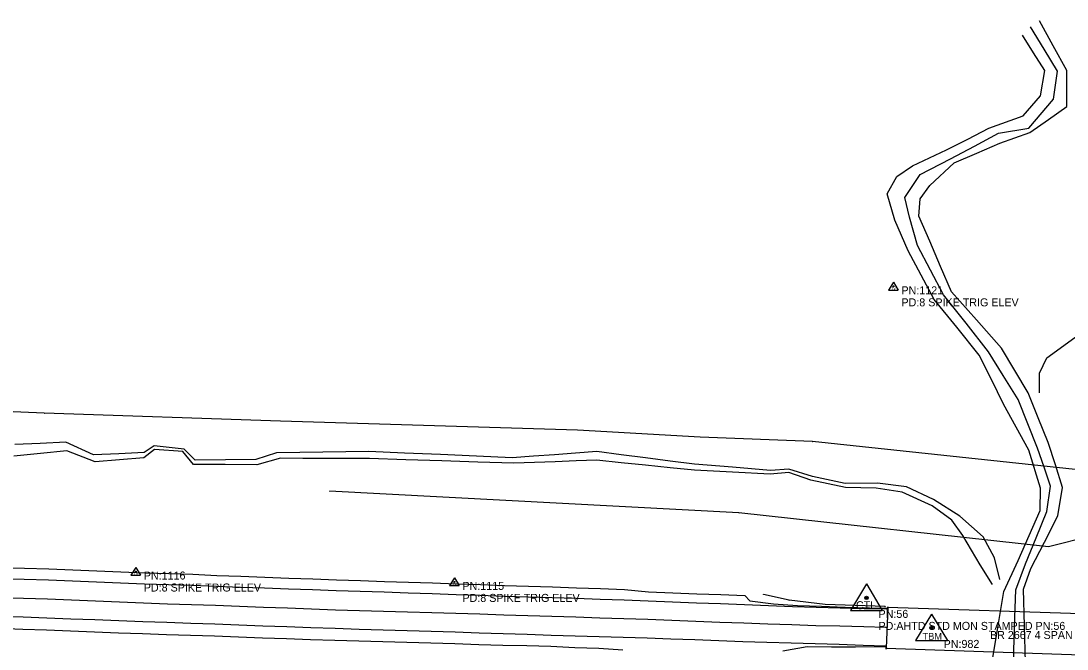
# Model space of a CAD drawing. Extents: x 976456 to 985170, y 1525951 to 1527080.
# Drawn here: x 977415 to 978069, y 1526484 to 1526877 of the extents above; entities that cross this region are included whole.
import ezdxf

# ---------------------------------------------------------------- set-up
doc = ezdxf.new("R2010")
doc.units = 0
for name, color, linetype in [('S_BRIDGE', 7, 'Continuous'), ('S_DITCHLINE', 7, 'Continuous'), ('S_EDGE_PAVEMENT', 7, 'Continuous'), ('S_FENCE', 7, 'Continuous'), ('S_FIBER_OPTIC_CABLE', 7, 'Continuous'), ('S_GUARDRAIL', 7, 'Continuous'), ('S_MSC_PT_SYM', 7, 'Continuous'), ('S_PAVEMENT_CROWN', 7, 'Continuous'), ('S_PRIMARY_CTL', 7, 'Continuous'), ('S_PRIMARY_CTL_ANNOT', 7, 'Continuous'), ('S_RDW_PT_SYM', 7, 'Continuous'), ('S_SECONDARY_CTL', 7, 'Continuous'), ('S_SECONDARY_CTL_ANNOT', 7, 'Continuous'), ('S_SHOULDER', 7, 'Continuous'), ('S_STR_PT_SYM', 7, 'Continuous'), ('S_STREAM', 7, 'Continuous'), ('S_SURVEY_TEXT_ANNOT', 7, 'Continuous'), ('S_UTL_PT_SYM', 7, 'Continuous')]:
    doc.layers.add(name, color=color, linetype=linetype)

msp = doc.modelspace()

# ---------------------------------------------------------------- linework, layer by layer
at = {"layer": 'S_BRIDGE'}
for p, q in [((977956.8, 1526510.36), (977955.86, 1526484.94)), ((978086.33, 1526506.14), (977956.8, 1526510.36)), ((977955.86, 1526484.94), (978085.38, 1526480.48))]:
    msp.add_line(p, q, dxfattribs=at)
at = {"layer": 'S_DITCHLINE'}
for points in [[(978022.11, 1526524.86), (978014.39, 1526537.02), (978003.69, 1526555.36), (977996.69, 1526565.09), (977984.55, 1526573.85), (977965.71, 1526582.4), (977949.52, 1526585.06), (977930.38, 1526585.35), (977908.76, 1526589.99), (977894.9, 1526594.7), (977883.34, 1526593.71), (977859.69, 1526594.95), (977836.03, 1526596.19), (977820.78, 1526597.75), (977805.53, 1526599.32), (977790.28, 1526600.89), (977775.03, 1526602.46), (977762.07, 1526601.98), (977749.12, 1526601.51), (977736.16, 1526601.04), (977723.21, 1526600.56), (977700.7, 1526601.29), (977678.19, 1526602.02), (977655.68, 1526602.75), (977633.17, 1526603.48), (977619.27, 1526603.52), (977605.36, 1526603.56), (977591.46, 1526603.6), (977577.56, 1526603.64), (977562.67, 1526599.67), (977542.95, 1526599.76), (977523.23, 1526599.86), (977516.49, 1526607.97), (977498.76, 1526609.15), (977492.06, 1526604.02), (977476.91, 1526602.69), (977461.76, 1526601.35), (977444.09, 1526608.43), (977427.49, 1526606.7), (977410.9, 1526604.96)], [(978026.79, 1526527.94), (978023.47, 1526541.45), (978016.39, 1526554.51), (978001.68, 1526567.51), (977985.38, 1526577.96), (977968.53, 1526585.8), (977950.35, 1526588.02), (977930.07, 1526587.85), (977909.81, 1526592.38), (977894.95, 1526596.84), (977883.6, 1526596.13), (977859.81, 1526598.05), (977836.03, 1526599.97), (977820.78, 1526601.94), (977805.53, 1526603.9), (977790.28, 1526605.86), (977775.03, 1526607.82), (977761.83, 1526606.87), (977748.62, 1526605.91), (977735.42, 1526604.95), (977722.21, 1526603.99), (977699.82, 1526604.98), (977677.42, 1526605.98), (977655.02, 1526606.97), (977632.63, 1526607.96), (977618.24, 1526607.75), (977603.85, 1526607.54), (977589.46, 1526607.33), (977575.08, 1526607.12), (977562.04, 1526602.91), (977543.17, 1526602.75), (977524.29, 1526602.59), (977517.31, 1526609.38), (977498.63, 1526611.49), (977492.41, 1526607.25), (977476.58, 1526606.54), (977460.76, 1526605.83), (977443.38, 1526613.68), (977427.48, 1526612.95), (977411.59, 1526612.21)]]:
    msp.add_lwpolyline(points, dxfattribs=at)
at = {"layer": 'S_EDGE_PAVEMENT'}
for points in [[(977402.36, 1526528.58), (977417.36, 1526528.07), (977432.54, 1526527.67), (977447.52, 1526527.06), (977462.51, 1526526.49), (977477.5, 1526525.88), (977492.49, 1526525.22), (977492.49, 1526525.22), (977492.49, 1526525.22), (977507.48, 1526524.75), (977522.45, 1526524.33), (977537.44, 1526523.77), (977552.43, 1526523.2), (977567.41, 1526522.62), (977582.4, 1526522.05), (977597.4, 1526521.6), (977597.4, 1526521.6), (977597.4, 1526521.6), (977612.28, 1526521.1), (977627.27, 1526520.57), (977642.26, 1526520.12), (977657.26, 1526519.63), (977672.24, 1526519.08), (977687.24, 1526518.58), (977702.26, 1526518.14), (977717.24, 1526517.58), (977732.24, 1526517.11), (977747.23, 1526516.64), (977762.22, 1526516.17), (977777.21, 1526515.69), (977792.2, 1526515.09), (977807.2, 1526514.63), (977822.29, 1526513.91), (977837.28, 1526513.41), (977852.27, 1526512.82), (977867.26, 1526512.19), (977882.25, 1526511.59), (977897.24, 1526511.04), (977912.07, 1526510.62), (977927.06, 1526510.2), (977942.06, 1526509.83), (977955.73, 1526509.47), (977956.7, 1526509.44)], [(977401.76, 1526505.02), (977416.76, 1526504.51), (977431.59, 1526504.02), (977446.58, 1526503.41), (977461.57, 1526502.84), (977476.56, 1526502.24), (977491.55, 1526501.71), (977506.54, 1526501.17), (977521.56, 1526500.69), (977536.55, 1526500.16), (977536.55, 1526500.16), (977551.54, 1526499.62), (977551.54, 1526499.62), (977566.52, 1526498.98), (977581.52, 1526498.47), (977596.51, 1526497.91), (977611.58, 1526497.39), (977626.58, 1526496.95), (977641.57, 1526496.49), (977641.57, 1526496.49), (977656.56, 1526496.05), (977671.56, 1526495.6), (977686.55, 1526495.16), (977701.52, 1526494.63), (977716.51, 1526494.13), (977731.5, 1526493.66), (977746.5, 1526493.17), (977761.49, 1526492.7), (977776.48, 1526492.31), (977791.48, 1526491.84), (977806.47, 1526491.38), (977821.37, 1526490.89), (977836.36, 1526490.32), (977851.35, 1526489.72), (977866.34, 1526489.23), (977881.33, 1526488.63), (977896.33, 1526488.24), (977911.45, 1526487.85), (977911.45, 1526487.85), (977911.45, 1526487.85), (977926.44, 1526487.39), (977941.44, 1526486.92), (977955.14, 1526486.51), (977955.78, 1526486.49)]]:
    msp.add_lwpolyline(points, dxfattribs=at)
at = {"layer": 'S_FENCE'}
for p, q in [((977429.97, 1526631.95), (977214.88, 1526641.2)), ((977577.45, 1526626.9), (977429.97, 1526631.95)), ((977762.93, 1526621.31), (977577.45, 1526626.9)), ((977839.57, 1526616.88), (977762.93, 1526621.31)), ((977909.7, 1526614.16), (977839.57, 1526616.88)), ((978230.77, 1526580), (977909.7, 1526614.16))]:
    msp.add_line(p, q, dxfattribs=at)
at = {"layer": 'S_FIBER_OPTIC_CABLE'}
for p, q in [((977863.85, 1526569.6), (977608.15, 1526583.08)), ((978057.17, 1526548.34), (977863.85, 1526569.6)), ((978103.59, 1526560.21), (978057.17, 1526548.34))]:
    msp.add_line(p, q, dxfattribs=at)
at = {"layer": 'S_GUARDRAIL'}
for p, q in [((977895.11, 1526515.01), (977879.11, 1526518.44)), ((977917.64, 1526512.3), (977895.11, 1526515.01)), ((977955.08, 1526510.96), (977917.64, 1526512.3))]:
    msp.add_line(p, q, dxfattribs=at)
at = {"layer": 'S_MSC_PT_SYM'}
for points in [[(977429.97, 1526631.95), (977429.97, 1526632), (977429.97, 1526631.95), (977429.92, 1526631.95), (977429.97, 1526631.95), (977429.97, 1526631.9), (977429.97, 1526631.95), (977430.02, 1526631.95)], [(977577.45, 1526626.9), (977577.45, 1526626.95), (977577.45, 1526626.9), (977577.4, 1526626.9), (977577.45, 1526626.9), (977577.45, 1526626.85), (977577.45, 1526626.9), (977577.5, 1526626.9)], [(977762.93, 1526621.31), (977762.93, 1526621.36), (977762.93, 1526621.31), (977762.88, 1526621.31), (977762.93, 1526621.31), (977762.93, 1526621.26), (977762.93, 1526621.31), (977762.98, 1526621.31)], [(977839.57, 1526616.88), (977839.57, 1526616.93), (977839.57, 1526616.88), (977839.52, 1526616.88), (977839.57, 1526616.88), (977839.57, 1526616.83), (977839.57, 1526616.88), (977839.62, 1526616.88)], [(977909.7, 1526614.16), (977909.7, 1526614.21), (977909.7, 1526614.16), (977909.65, 1526614.16), (977909.7, 1526614.16), (977909.7, 1526614.11), (977909.7, 1526614.16), (977909.75, 1526614.16)], [(978020.61, 1526495.7), (978020.61, 1526495.75), (978020.61, 1526495.7), (978020.56, 1526495.7), (978020.61, 1526495.7), (978020.61, 1526495.65), (978020.61, 1526495.7), (978020.66, 1526495.7)]]:
    msp.add_lwpolyline(points, dxfattribs=at)
at = {"layer": 'S_PAVEMENT_CROWN'}
for points in [[(977402.06, 1526516.56), (977417.05, 1526516.17), (977432.06, 1526515.75), (977447.05, 1526515.1), (977462.04, 1526514.51), (977477.02, 1526513.91), (977492.01, 1526513.34), (977507, 1526512.79), (977521.99, 1526512.31), (977536.99, 1526511.83), (977551.97, 1526511.25), (977566.96, 1526510.69), (977581.95, 1526510.12), (977596.94, 1526509.56), (977611.92, 1526509.01), (977626.92, 1526508.57), (977641.91, 1526508.13), (977656.91, 1526507.71), (977671.9, 1526507.28), (977686.89, 1526506.83), (977701.89, 1526506.34), (977716.88, 1526505.87), (977731.87, 1526505.4), (977746.86, 1526504.93), (977761.86, 1526504.47), (977776.85, 1526503.94), (977791.84, 1526503.48), (977806.83, 1526503.01), (977821.83, 1526502.45), (977836.82, 1526501.87), (977851.81, 1526501.28), (977866.8, 1526500.77), (977881.79, 1526500.18), (977896.78, 1526499.72), (977911.76, 1526499.24), (977926.75, 1526498.86), (977941.75, 1526498.5), (977955.44, 1526498.14)], [(977955.44, 1526498.14), (977956.23, 1526498.12)]]:
    msp.add_lwpolyline(points, dxfattribs=at)
at = {"layer": 'S_PRIMARY_CTL'}
for p, q in [((977943.49, 1526525.1), (977933.46, 1526508.59)), ((977943.49, 1526525.1), (977953.32, 1526508.59)), ((977933.46, 1526508.59), (977953.32, 1526508.59)), ((977984.17, 1526506.33), (977974.13, 1526489.82)), ((977984.17, 1526506.33), (977993.99, 1526489.82)), ((977974.13, 1526489.82), (977993.99, 1526489.82))]:
    msp.add_line(p, q, dxfattribs=at)
for centre, radius in [((977943.49, 1526516.4), 1.04), ((977943.49, 1526516.4), 0.609), ((977943.49, 1526516.4), 0.344), ((977984.17, 1526497.63), 1.04), ((977984.17, 1526497.63), 0.609), ((977984.17, 1526497.63), 0.344)]:
    msp.add_circle(centre, radius, dxfattribs=at)
at = {"layer": 'S_RDW_PT_SYM'}
for points in [[(977879.11, 1526518.44), (977879.11, 1526518.49), (977879.11, 1526518.44), (977879.06, 1526518.44), (977879.11, 1526518.44), (977879.11, 1526518.39), (977879.11, 1526518.44), (977879.16, 1526518.44)], [(977895.11, 1526515.01), (977895.11, 1526515.06), (977895.11, 1526515.01), (977895.06, 1526515.01), (977895.11, 1526515.01), (977895.11, 1526514.96), (977895.11, 1526515.01), (977895.16, 1526515.01)], [(977917.64, 1526512.3), (977917.64, 1526512.35), (977917.64, 1526512.3), (977917.59, 1526512.3), (977917.64, 1526512.3), (977917.64, 1526512.25), (977917.64, 1526512.3), (977917.69, 1526512.3)], [(977955.08, 1526510.96), (977955.08, 1526511.01), (977955.08, 1526510.96), (977955.03, 1526510.96), (977955.08, 1526510.96), (977955.08, 1526510.91), (977955.08, 1526510.96), (977955.13, 1526510.96)]]:
    msp.add_lwpolyline(points, dxfattribs=at)
at = {"layer": 'S_SECONDARY_CTL'}
for p, q in [((977960.32, 1526713.76), (977957.31, 1526708.81)), ((977960.32, 1526713.76), (977963.26, 1526708.81)), ((977957.31, 1526708.81), (977963.26, 1526708.81)), ((977487.11, 1526535.5), (977484.1, 1526530.55)), ((977484.1, 1526530.55), (977490.05, 1526530.55)), ((977487.11, 1526535.5), (977490.05, 1526530.55)), ((977686.13, 1526529), (977683.12, 1526524.05)), ((977683.12, 1526524.05), (977689.08, 1526524.05)), ((977686.13, 1526529), (977689.08, 1526524.05))]:
    msp.add_line(p, q, dxfattribs=at)
for centre, radius in [((977960.32, 1526711.15), 0.311), ((977960.32, 1526711.15), 0.183), ((977960.32, 1526711.15), 0.103), ((977487.11, 1526532.89), 0.311), ((977487.11, 1526532.89), 0.183), ((977487.11, 1526532.89), 0.103), ((977686.13, 1526526.39), 0.311), ((977686.13, 1526526.39), 0.183), ((977686.13, 1526526.39), 0.103)]:
    msp.add_circle(centre, radius, dxfattribs=at)
at = {"layer": 'S_SHOULDER'}
for points in [[(977402.54, 1526535.38), (977417.53, 1526534.88), (977432.81, 1526534.48), (977447.8, 1526533.86), (977462.78, 1526533.3), (977477.77, 1526532.68), (977492.76, 1526532.03), (977507.75, 1526531.55), (977522.7, 1526531.13), (977537.69, 1526530.45), (977552.68, 1526529.88), (977567.67, 1526529.3), (977582.66, 1526528.74), (977597.65, 1526528.28), (977612.48, 1526527.79), (977627.47, 1526527.26), (977642.46, 1526526.74), (977657.45, 1526526.25), (977672.44, 1526525.71), (977687.43, 1526525.23), (977702.46, 1526524.79), (977717.45, 1526524.23), (977732.45, 1526523.76), (977747.44, 1526523.26), (977762.43, 1526522.78), (977777.42, 1526522.29), (977792.41, 1526521.67), (977807.37, 1526520.24), (977822.52, 1526519.49), (977837.51, 1526519.03), (977852.5, 1526518.44), (977867.48, 1526517.81), (977870.55, 1526514.59), (977885.49, 1526512.72), (977900.46, 1526511.7), (977915.28, 1526511.3), (977930.26, 1526510.64), (977945.26, 1526510.28), (977956.71, 1526509.97)], [(977401.58, 1526497.45), (977416.57, 1526496.94), (977431.3, 1526496.4), (977446.29, 1526495.8), (977461.28, 1526495.23), (977476.27, 1526494.64), (977491.26, 1526494.11), (977506.25, 1526493.57), (977521.28, 1526493.14), (977536.27, 1526492.58), (977551.26, 1526492.05), (977566.25, 1526491.49), (977581.24, 1526490.97), (977596.23, 1526490.42), (977611.37, 1526489.89), (977626.36, 1526489.54), (977641.36, 1526489.16), (977656.35, 1526488.72), (977671.35, 1526488.27), (977686.34, 1526487.82), (977701.3, 1526487.26), (977716.3, 1526486.94), (977731.3, 1526486.74), (977746.29, 1526486.19), (977761.27, 1526485.48), (977776.26, 1526484.99), (977791.24, 1526483.97)], [(977891.25, 1526483.24), (977906.37, 1526485.99), (977921.53, 1526485.81), (977936.53, 1526485.74), (977951.54, 1526485.98), (977955.77, 1526485.87)]]:
    msp.add_lwpolyline(points, dxfattribs=at)
at = {"layer": 'S_STR_PT_SYM'}
for points in [[(977956.8, 1526510.36), (977956.8, 1526510.86), (977956.8, 1526510.36), (977956.3, 1526510.36), (977956.8, 1526510.36), (977956.8, 1526509.86), (977956.8, 1526510.36), (977957.3, 1526510.36)], [(977955.86, 1526484.94), (977955.86, 1526485.44), (977955.86, 1526484.94), (977955.36, 1526484.94), (977955.86, 1526484.94), (977955.86, 1526484.44), (977955.86, 1526484.94), (977956.36, 1526484.94)]]:
    msp.add_lwpolyline(points, dxfattribs=at)
at = {"layer": 'S_STREAM'}
for points in [[(978042.77, 1526476.04), (978042.11, 1526498.99), (978041.46, 1526521.94), (978046.14, 1526534.73), (978054.59, 1526551.18), (978063.04, 1526567.63), (978065.84, 1526585.49), (978061.44, 1526599.54), (978057.05, 1526613.59), (978050.72, 1526629.05), (978044.4, 1526644.5), (978036.13, 1526658.53), (978027.86, 1526672.55), (978012.22, 1526690.17), (977996.58, 1526707.8), (977989.77, 1526723.64), (977982.96, 1526739.48), (977976.2, 1526755.05), (977976.91, 1526765.91), (977983.05, 1526774.18), (977998.21, 1526788.4), (978012.49, 1526794.5), (978026.77, 1526800.6), (978045.58, 1526807.33), (978057.12, 1526815.43), (978068.67, 1526823.52), (978068.62, 1526846.01), (978060.05, 1526861.55), (978051.48, 1526877.08)], [(978035.3, 1526475.42), (978036, 1526498.48), (978036.71, 1526521.54), (978042.8, 1526537.69), (978049.49, 1526554.02), (978056.19, 1526570.34), (978058.38, 1526586.31), (978054.36, 1526598.19), (978050.35, 1526610.06), (978044.3, 1526625.29), (978038.24, 1526640.52), (978028.94, 1526655.42), (978019.64, 1526670.31), (978005.63, 1526688.1), (977991.63, 1526705.88), (977983.49, 1526721.33), (977975.35, 1526736.78), (977970.3, 1526754.39), (977967.34, 1526766.61), (977977.03, 1526781.11), (977995.97, 1526790.88), (978010.96, 1526798.84), (978025.95, 1526806.81), (978044.85, 1526809.99), (978060.34, 1526828.13), (978062.88, 1526845.57), (978054.43, 1526859.44), (978045.98, 1526873.31)], [(978021.86, 1526475.24), (978025.61, 1526497.86), (978029.36, 1526520.49), (978038.17, 1526539.69), (978045.09, 1526555.35), (978052.01, 1526571.01), (978052.09, 1526585.04), (978044.92, 1526608.75), (978037.03, 1526623.09), (978029.14, 1526637.42), (978021.46, 1526652.82), (978013.77, 1526668.22), (977999.8, 1526685.62), (977985.82, 1526703.03), (977977.64, 1526718.21), (977969.45, 1526733.4), (977961.21, 1526752.44), (977956.29, 1526769.03), (977962.34, 1526779.75), (977972.14, 1526786.48), (977993.46, 1526796.53), (978006.71, 1526803.25), (978019.96, 1526809.98), (978041.38, 1526817.65), (978052.12, 1526830.29), (978054.92, 1526846.03), (978047.88, 1526857.06), (978040.85, 1526868.08)], [(978051.61, 1526644.56), (978051.47, 1526656.9), (978056.04, 1526666.46), (978073.63, 1526679.08), (978085.9, 1526686.45), (978103.09, 1526697.07), (978108.45, 1526699.25), (978124.96, 1526696.31), (978132.54, 1526691.99), (978146.67, 1526680.45), (978149.59, 1526673.07), (978149.89, 1526658.56), (978150.2, 1526644.04), (978153.95, 1526620.4), (978163.31, 1526605.37), (978175.04, 1526590.51), (978182.89, 1526583.96), (978193.91, 1526583), (978201.74, 1526589.46), (978212.39, 1526598.76), (978224.11, 1526599.13), (978235.18, 1526589.12), (978247.18, 1526594.64), (978250.22, 1526603.22)]]:
    msp.add_lwpolyline(points, dxfattribs=at)
at = {"layer": 'S_UTL_PT_SYM'}
for points in [[(977608.15, 1526583.08), (977608.15, 1526583.13), (977608.15, 1526583.08), (977608.1, 1526583.08), (977608.15, 1526583.08), (977608.15, 1526583.03), (977608.15, 1526583.08), (977608.2, 1526583.08)], [(977863.85, 1526569.6), (977863.85, 1526569.65), (977863.85, 1526569.6), (977863.8, 1526569.6), (977863.85, 1526569.6), (977863.85, 1526569.55), (977863.85, 1526569.6), (977863.9, 1526569.6)], [(978057.17, 1526548.34), (978057.17, 1526548.39), (978057.17, 1526548.34), (978057.12, 1526548.34), (978057.17, 1526548.34), (978057.17, 1526548.29), (978057.17, 1526548.34), (978057.22, 1526548.34)]]:
    msp.add_lwpolyline(points, dxfattribs=at)

# ---------------------------------------------------------------- texts
at = {"layer": 'S_PRIMARY_CTL'}
for s, height, p in [('CTL', 5, (977936.91, 1526509.32)), ('TBM', 4.287, (977978.51, 1526490.24))]:
    msp.add_text(s, height=height, rotation=360, dxfattribs=at).set_placement(p)
at = {"layer": 'S_PRIMARY_CTL_ANNOT'}
for s, p in [('PN:56', (977950.99, 1526503.9)), ('PD:AHTD STD MON STAMPED PN:56', (977950.99, 1526496.4)), ('PN:982', (977991.67, 1526485.13))]:
    msp.add_text(s, height=5, dxfattribs=at).set_placement(p)
at = {"layer": 'S_SECONDARY_CTL'}
for p in [(977959.11, 1526709.14), (977485.9, 1526530.88), (977684.93, 1526524.38)]:
    msp.add_text('TV', height=1.5, rotation=360, dxfattribs=at).set_placement(p)
at = {"layer": 'S_SECONDARY_CTL_ANNOT'}
for s, p in [('PN:1121', (977965.32, 1526706.15)), ('PD:8 SPIKE TRIG ELEV', (977965.32, 1526698.65)), ('PN:1116', (977492.11, 1526527.89)), ('PD:8 SPIKE TRIG ELEV', (977492.11, 1526520.39)), ('PN:1115', (977691.13, 1526521.39)), ('PD:8 SPIKE TRIG ELEV', (977691.13, 1526513.89))]:
    msp.add_text(s, height=5, dxfattribs=at).set_placement(p)
at = {"layer": 'S_SURVEY_TEXT_ANNOT'}
msp.add_text('BR 2667 4 SPAN STEEL/', height=5, dxfattribs=at).set_placement((978020.61, 1526490.7))

doc.saveas('drawing.dxf')
